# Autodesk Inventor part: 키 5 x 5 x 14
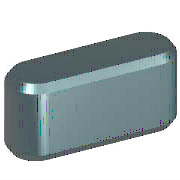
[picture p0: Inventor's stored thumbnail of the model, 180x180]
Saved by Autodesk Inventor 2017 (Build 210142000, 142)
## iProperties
IsCustomPart: 1
Created: 2012-02
Part Number: 키 5 x 5 x 14
Material: 강철, 연강
Description: 키 및 해당 키홈
Document SubType Name: Modeling
Standard: KS B 1311
Designer: mduedu
Standards Organization: KS
Language: ko-KR
Size Designation: 5 x 5 x 14
Categories: <MemberInstance><Categories><Category DisplayName="샤프트 부품" InternalName="7f7aeb1f-a693-4053-b835-cee3144e0d98" Mnemonic="SHFT"><Category DisplayName="키" Interna
Density: 1 g/cm^3
Appearance: 노란색
Author: mduedu
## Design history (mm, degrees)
workplane "Work Plane1"
workplane "Work Plane2"
sketch "스케치1"
  geometry: L1 (2.5, 2.5)-(11.5, 2.5); L2 (11.5, -2.5)-(2.5, -2.5); L3 (0, 9.4)-(0, -7.4) reference; L4 (-5, 0)-(30, 0) reference; L5 (14, 0)-(14, 7); A1 r 2.5 centre (2.5, 0) between (2.5, 2.5) and (2.5, -2.5); A2 r 2.5 centre (11.5, 0) between (11.5, -2.5) and (11.5, 2.5)
  constraints: 6 end point, 5 point on circle, 4 tangent, 3 point on line, 2 centre point, 1 horizontal, 1 parallel, 1 perpendicular
  dimensions: "d0" = 2.5 radius of A1 (= 0.5 x PB); "d13" = 2.5 radius of A2 (= 0.5 x PB); "d14" = 14 distance between parallel lines of L5 L3 (= NLG)
extrude "본체1" new body sketch "스케치1" taper "d3" = 0 deg; stored distance "d4" = 10
workplane "Work Plane3"
body "Solid1"
chamfer "모따기1" distance "d8" = 0.4 (= PHH); stored, may be unused: second distance "d9" = 0.4 (= PHH), angle "d15" = 45 deg
other parameters: "d1" = -3 (= -PNT), "d2" = 2 (= PH - PNT), "NLG" = 14 [user parameter; used in 3 equation terms], "PB" = 5 [user parameter; used in 2 equation terms], "PNT" = 3 [user parameter; used in 2 equation terms], "PH" = 5 [user parameter; used in 1 equation term], "PHH" = 0.4 [user parameter; used in 2 equation terms], "d10" = 0, "d16" = 0, "d17" = 0, "d18" = 0, "WDMIN" = 12 [user parameter], "PLB2" = 14 (= NLG) [user parameter], "WDMAX" = 17 [user parameter], "PLB1" = 14 (= NLG) [user parameter], "RR" = 0.16 [user parameter], "PUEB" = 2.3 [user parameter]
